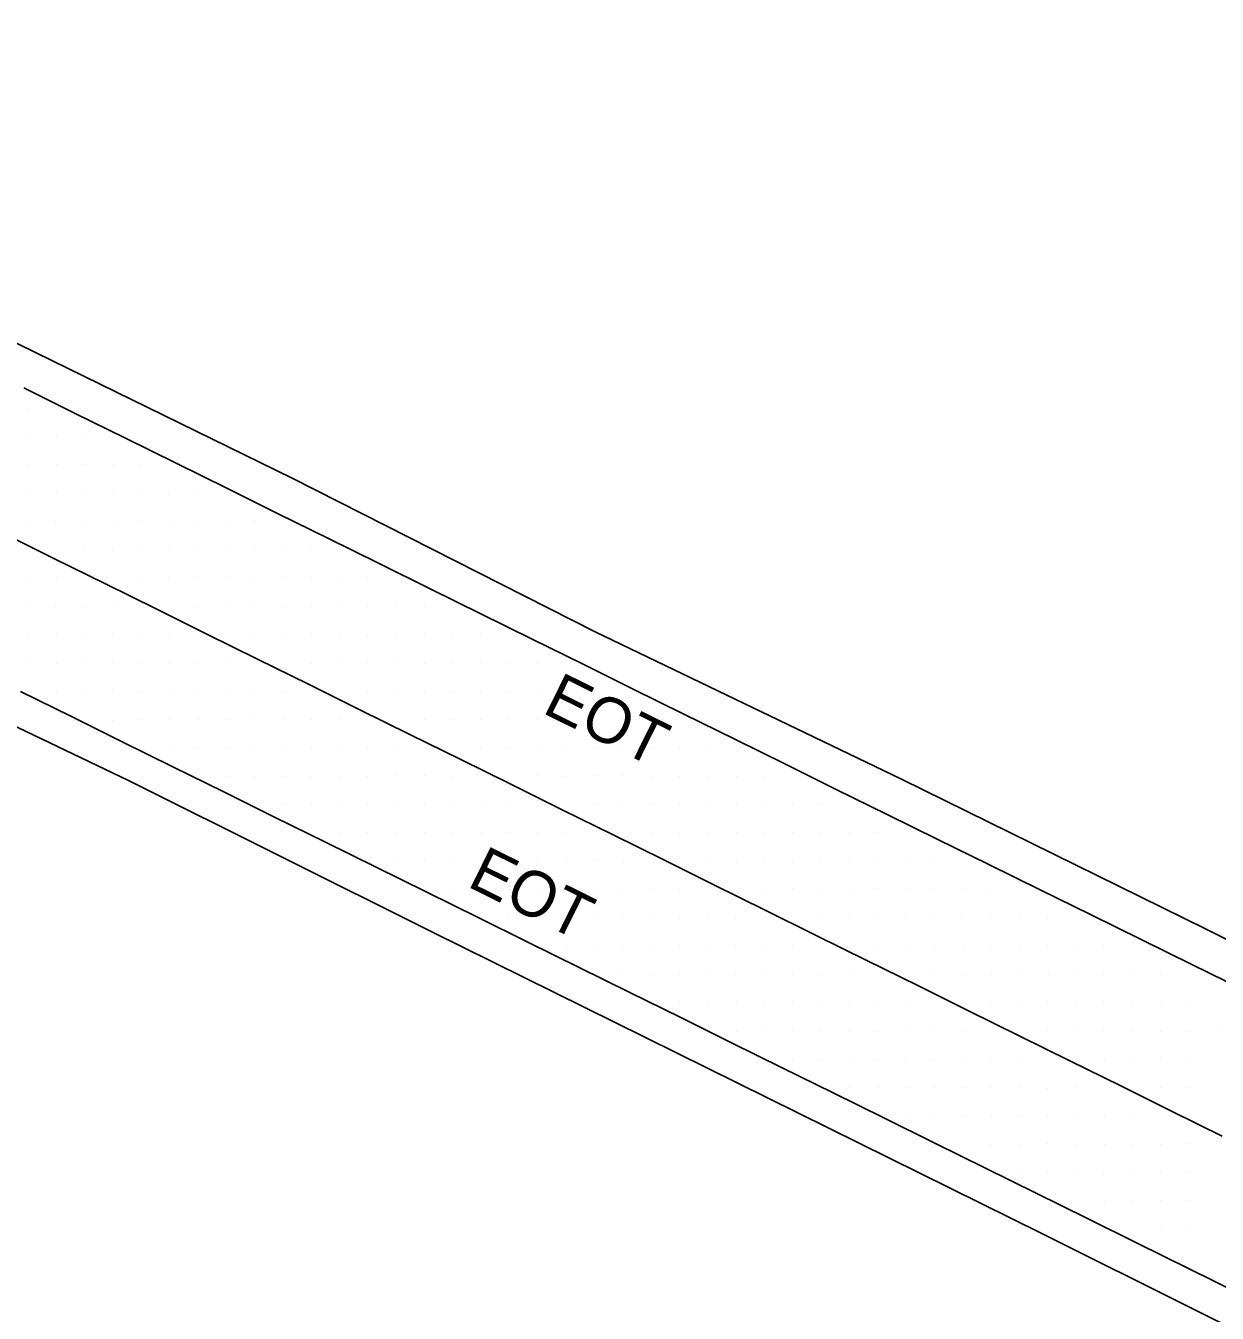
# Model space of a CAD drawing. Extents: x 2244337 to 2251208, y 199469 to 202984.
# Drawn here: x 2245321.4 to 2245426.6, y 202410.3 to 202524 of the extents above; entities that cross this region are included whole.
import ezdxf

# ---------------------------------------------------------------- set-up
doc = ezdxf.new("R2010")
doc.units = 0
for name, color, linetype in [('Exist DTM Scan Elevation Point', 7, 'Continuous'), ('Exist EOT Text', 7, 'Continuous'), ('Exist Roads EOP', 7, 'Continuous'), ('Exist Roads EOT', 7, 'Continuous')]:
    doc.layers.add(name, color=color, linetype=linetype)

msp = doc.modelspace()

# ---------------------------------------------------------------- linework, layer by layer
at = {"layer": 'Exist DTM Scan Elevation Point'}
for p, q in [((2245321.59, 202490.19), (2245321.59, 202490.19)), ((2245321.56, 202487.7), (2245321.56, 202487.7)), ((2245324.14, 202487.68), (2245324.14, 202487.68)), ((2245326.56, 202487.72), (2245326.56, 202487.72)), ((2245321.58, 202485.23), (2245321.58, 202485.23)), ((2245324.08, 202485.2), (2245324.08, 202485.2)), ((2245326.62, 202485.25), (2245326.62, 202485.25)), ((2245329.09, 202485.25), (2245329.09, 202485.25)), ((2245331.53, 202485.21), (2245331.53, 202485.21)), ((2245321.51, 202482.74), (2245321.51, 202482.74)), ((2245324.1, 202482.74), (2245324.1, 202482.74)), ((2245326.55, 202482.71), (2245326.55, 202482.71)), ((2245329.1, 202482.69), (2245329.1, 202482.69)), ((2245331.56, 202482.69), (2245331.56, 202482.69)), ((2245334.01, 202482.66), (2245334.01, 202482.66)), ((2245336.63, 202482.75), (2245336.63, 202482.75)), ((2245321.58, 202480.15), (2245321.58, 202480.15)), ((2245324.01, 202480.17), (2245324.01, 202480.17)), ((2245326.57, 202480.2), (2245326.57, 202480.2)), ((2245329.1, 202480.21), (2245329.1, 202480.21)), ((2245331.57, 202480.2), (2245331.57, 202480.2)), ((2245334.07, 202480.2), (2245334.07, 202480.2)), ((2245336.6, 202480.22), (2245336.6, 202480.22)), ((2245339.06, 202480.19), (2245339.06, 202480.19)), ((2245341.61, 202480.24), (2245341.61, 202480.24)), ((2245326.56, 202477.74), (2245326.56, 202477.74)), ((2245329.06, 202477.74), (2245329.06, 202477.74)), ((2245331.57, 202477.74), (2245331.57, 202477.74)), ((2245334.05, 202477.76), (2245334.05, 202477.76)), ((2245336.55, 202477.72), (2245336.55, 202477.72)), ((2245339.08, 202477.73), (2245339.08, 202477.73)), ((2245341.57, 202477.69), (2245341.57, 202477.69)), ((2245344.05, 202477.73), (2245344.05, 202477.73)), ((2245346.54, 202477.72), (2245346.54, 202477.72)), ((2245321.55, 202475.21), (2245321.55, 202475.21)), ((2245324.09, 202475.21), (2245324.09, 202475.21)), ((2245331.59, 202475.19), (2245331.59, 202475.19)), ((2245334, 202475.19), (2245334, 202475.19)), ((2245336.57, 202475.22), (2245336.57, 202475.22)), ((2245339.09, 202475.22), (2245339.09, 202475.22)), ((2245341.56, 202475.22), (2245341.56, 202475.22)), ((2245344.08, 202475.22), (2245344.08, 202475.22)), ((2245346.58, 202475.25), (2245346.58, 202475.25)), ((2245349.09, 202475.26), (2245349.09, 202475.26)), ((2245351.57, 202475.21), (2245351.57, 202475.21)), ((2245321.6, 202472.72), (2245321.6, 202472.72)), ((2245324.05, 202472.71), (2245324.05, 202472.71)), ((2245326.63, 202472.67), (2245326.63, 202472.67)), ((2245329.09, 202472.71), (2245329.09, 202472.71)), ((2245336.55, 202472.72), (2245336.55, 202472.72)), ((2245339.06, 202472.68), (2245339.06, 202472.68)), ((2245341.59, 202472.72), (2245341.59, 202472.72)), ((2245344.07, 202472.69), (2245344.07, 202472.69)), ((2245346.58, 202472.68), (2245346.58, 202472.68)), ((2245349.08, 202472.71), (2245349.08, 202472.71)), ((2245351.59, 202472.76), (2245351.59, 202472.76)), ((2245354.1, 202472.74), (2245354.1, 202472.74)), ((2245356.58, 202472.71), (2245356.58, 202472.71)), ((2245321.56, 202470.23), (2245321.56, 202470.23)), ((2245324.1, 202470.18), (2245324.1, 202470.18)), ((2245326.59, 202470.16), (2245326.59, 202470.16)), ((2245329.07, 202470.21), (2245329.07, 202470.21)), ((2245331.57, 202470.23), (2245331.57, 202470.23)), ((2245334.05, 202470.24), (2245334.05, 202470.24)), ((2245341.58, 202470.15), (2245341.58, 202470.15)), ((2245344.08, 202470.18), (2245344.08, 202470.18)), ((2245346.6, 202470.24), (2245346.6, 202470.24)), ((2245349.04, 202470.18), (2245349.04, 202470.18)), ((2245351.59, 202470.17), (2245351.59, 202470.17)), ((2245354.08, 202470.22), (2245354.08, 202470.22)), ((2245356.54, 202470.25), (2245356.54, 202470.25)), ((2245359.04, 202470.23), (2245359.04, 202470.23)), ((2245361.54, 202470.22), (2245361.54, 202470.22)), ((2245321.55, 202467.73), (2245321.55, 202467.73)), ((2245324.09, 202467.69), (2245324.09, 202467.69)), ((2245326.56, 202467.76), (2245326.56, 202467.76)), ((2245329.06, 202467.71), (2245329.06, 202467.71)), ((2245331.56, 202467.71), (2245331.56, 202467.71)), ((2245334.1, 202467.68), (2245334.1, 202467.68)), ((2245336.57, 202467.72), (2245336.57, 202467.72)), ((2245339.06, 202467.7), (2245339.06, 202467.7)), ((2245346.57, 202467.68), (2245346.57, 202467.68)), ((2245349.09, 202467.74), (2245349.09, 202467.74)), ((2245351.51, 202467.75), (2245351.51, 202467.75)), ((2245354.09, 202467.73), (2245354.09, 202467.73)), ((2245356.58, 202467.68), (2245356.58, 202467.68)), ((2245359.07, 202467.66), (2245359.07, 202467.66)), ((2245361.56, 202467.71), (2245361.56, 202467.71)), ((2245364.08, 202467.72), (2245364.08, 202467.72)), ((2245366.59, 202467.68), (2245366.59, 202467.68)), ((2245324.08, 202465.2), (2245324.08, 202465.2)), ((2245326.57, 202465.21), (2245326.57, 202465.21)), ((2245329.08, 202465.25), (2245329.08, 202465.25)), ((2245331.56, 202465.22), (2245331.56, 202465.22)), ((2245334.08, 202465.19), (2245334.08, 202465.19)), ((2245336.6, 202465.21), (2245336.6, 202465.21)), ((2245339.05, 202465.22), (2245339.05, 202465.22)), ((2245341.59, 202465.18), (2245341.59, 202465.18)), ((2245344.09, 202465.19), (2245344.09, 202465.19)), ((2245351.53, 202465.2), (2245351.53, 202465.2)), ((2245354.02, 202465.18), (2245354.02, 202465.18)), ((2245356.54, 202465.18), (2245356.54, 202465.18)), ((2245359.11, 202465.2), (2245359.11, 202465.2)), ((2245361.56, 202465.19), (2245361.56, 202465.19)), ((2245364.07, 202465.21), (2245364.07, 202465.21)), ((2245366.61, 202465.24), (2245366.61, 202465.24)), ((2245369.08, 202465.23), (2245369.08, 202465.23)), ((2245371.58, 202465.24), (2245371.58, 202465.24)), ((2245329.07, 202462.65), (2245329.07, 202462.65)), ((2245331.57, 202462.73), (2245331.57, 202462.73)), ((2245334.07, 202462.72), (2245334.07, 202462.72)), ((2245336.61, 202462.7), (2245336.61, 202462.7)), ((2245339.07, 202462.71), (2245339.07, 202462.71)), ((2245341.58, 202462.79), (2245341.58, 202462.79)), ((2245344.1, 202462.72), (2245344.1, 202462.72)), ((2245346.58, 202462.74), (2245346.58, 202462.74)), ((2245349.1, 202462.73), (2245349.1, 202462.73)), ((2245356.56, 202462.68), (2245356.56, 202462.68)), ((2245359.1, 202462.71), (2245359.1, 202462.71)), ((2245361.57, 202462.7), (2245361.57, 202462.7)), ((2245364.04, 202462.71), (2245364.04, 202462.71)), ((2245366.58, 202462.67), (2245366.58, 202462.67)), ((2245369.09, 202462.67), (2245369.09, 202462.67)), ((2245371.59, 202462.66), (2245371.59, 202462.66)), ((2245374.08, 202462.74), (2245374.08, 202462.74)), ((2245376.57, 202462.69), (2245376.57, 202462.69)), ((2245334.08, 202460.22), (2245334.08, 202460.22)), ((2245336.58, 202460.22), (2245336.58, 202460.22)), ((2245339.11, 202460.24), (2245339.11, 202460.24)), ((2245341.57, 202460.21), (2245341.57, 202460.21)), ((2245344.1, 202460.19), (2245344.1, 202460.19)), ((2245346.6, 202460.22), (2245346.6, 202460.22)), ((2245349.14, 202460.16), (2245349.14, 202460.16)), ((2245351.58, 202460.25), (2245351.58, 202460.25)), ((2245354.05, 202460.22), (2245354.05, 202460.22)), ((2245361.54, 202460.22), (2245361.54, 202460.22)), ((2245364.07, 202460.2), (2245364.07, 202460.2)), ((2245366.59, 202460.21), (2245366.59, 202460.21)), ((2245369.11, 202460.2), (2245369.11, 202460.2)), ((2245371.55, 202460.2), (2245371.55, 202460.2)), ((2245374.07, 202460.21), (2245374.07, 202460.21)), ((2245376.55, 202460.26), (2245376.55, 202460.26)), ((2245379.1, 202460.2), (2245379.1, 202460.2)), ((2245381.55, 202460.19), (2245381.55, 202460.19)), ((2245339.1, 202457.72), (2245339.1, 202457.72)), ((2245341.61, 202457.69), (2245341.61, 202457.69)), ((2245344.05, 202457.7), (2245344.05, 202457.7)), ((2245346.55, 202457.69), (2245346.55, 202457.69)), ((2245349.13, 202457.72), (2245349.13, 202457.72)), ((2245351.55, 202457.7), (2245351.55, 202457.7)), ((2245354.08, 202457.74), (2245354.08, 202457.74)), ((2245356.58, 202457.74), (2245356.58, 202457.74)), ((2245359.08, 202457.67), (2245359.08, 202457.67)), ((2245366.52, 202457.73), (2245366.52, 202457.73)), ((2245369.04, 202457.69), (2245369.04, 202457.69)), ((2245371.57, 202457.75), (2245371.57, 202457.75)), ((2245374.05, 202457.75), (2245374.05, 202457.75)), ((2245376.61, 202457.71), (2245376.61, 202457.71)), ((2245379.05, 202457.67), (2245379.05, 202457.67)), ((2245381.54, 202457.67), (2245381.54, 202457.67)), ((2245384.11, 202457.72), (2245384.11, 202457.72)), ((2245386.57, 202457.69), (2245386.57, 202457.69)), ((2245344.08, 202455.21), (2245344.08, 202455.21)), ((2245346.57, 202455.22), (2245346.57, 202455.22)), ((2245349.09, 202455.26), (2245349.09, 202455.26)), ((2245351.58, 202455.24), (2245351.58, 202455.24)), ((2245354.05, 202455.26), (2245354.05, 202455.26)), ((2245356.54, 202455.2), (2245356.54, 202455.2)), ((2245359.06, 202455.26), (2245359.06, 202455.26)), ((2245361.62, 202455.21), (2245361.62, 202455.21)), ((2245364.04, 202455.21), (2245364.04, 202455.21)), ((2245371.56, 202455.22), (2245371.56, 202455.22)), ((2245374.09, 202455.19), (2245374.09, 202455.19)), ((2245376.55, 202455.18), (2245376.55, 202455.18)), ((2245379.06, 202455.2), (2245379.06, 202455.2)), ((2245381.6, 202455.2), (2245381.6, 202455.2)), ((2245384.09, 202455.25), (2245384.09, 202455.25)), ((2245386.6, 202455.21), (2245386.6, 202455.21)), ((2245389.05, 202455.22), (2245389.05, 202455.22)), ((2245391.62, 202455.22), (2245391.62, 202455.22)), ((2245349.07, 202452.71), (2245349.07, 202452.71)), ((2245351.59, 202452.75), (2245351.59, 202452.75)), ((2245354.12, 202452.69), (2245354.12, 202452.69)), ((2245356.56, 202452.71), (2245356.56, 202452.71)), ((2245359.05, 202452.73), (2245359.05, 202452.73)), ((2245361.61, 202452.72), (2245361.61, 202452.72)), ((2245364.06, 202452.71), (2245364.06, 202452.71)), ((2245366.57, 202452.76), (2245366.57, 202452.76)), ((2245369.06, 202452.68), (2245369.06, 202452.68)), ((2245376.61, 202452.73), (2245376.61, 202452.73)), ((2245379.07, 202452.68), (2245379.07, 202452.68)), ((2245381.58, 202452.7), (2245381.58, 202452.7)), ((2245384.09, 202452.74), (2245384.09, 202452.74)), ((2245386.56, 202452.74), (2245386.56, 202452.74)), ((2245389.04, 202452.69), (2245389.04, 202452.69)), ((2245391.56, 202452.71), (2245391.56, 202452.71)), ((2245394.11, 202452.71), (2245394.11, 202452.71)), ((2245396.58, 202452.69), (2245396.58, 202452.69)), ((2245354.14, 202450.25), (2245354.14, 202450.25)), ((2245356.55, 202450.22), (2245356.55, 202450.22)), ((2245359.04, 202450.24), (2245359.04, 202450.24)), ((2245361.58, 202450.22), (2245361.58, 202450.22)), ((2245364.07, 202450.21), (2245364.07, 202450.21)), ((2245366.55, 202450.17), (2245366.55, 202450.17)), ((2245369.08, 202450.21), (2245369.08, 202450.21)), ((2245371.58, 202450.23), (2245371.58, 202450.23)), ((2245374.16, 202450.21), (2245374.16, 202450.21)), ((2245381.59, 202450.24), (2245381.59, 202450.24)), ((2245384.1, 202450.21), (2245384.1, 202450.21)), ((2245386.55, 202450.2), (2245386.55, 202450.2)), ((2245389.07, 202450.21), (2245389.07, 202450.21)), ((2245391.54, 202450.18), (2245391.54, 202450.18)), ((2245394.09, 202450.21), (2245394.09, 202450.21)), ((2245396.58, 202450.2), (2245396.58, 202450.2)), ((2245399.08, 202450.25), (2245399.08, 202450.25)), ((2245401.57, 202450.23), (2245401.57, 202450.23)), ((2245359.09, 202447.71), (2245359.09, 202447.71)), ((2245361.58, 202447.73), (2245361.58, 202447.73)), ((2245364.05, 202447.72), (2245364.05, 202447.72)), ((2245366.6, 202447.69), (2245366.6, 202447.69)), ((2245369.04, 202447.72), (2245369.04, 202447.72)), ((2245371.54, 202447.73), (2245371.54, 202447.73)), ((2245374.07, 202447.7), (2245374.07, 202447.7)), ((2245376.52, 202447.71), (2245376.52, 202447.71)), ((2245379.11, 202447.72), (2245379.11, 202447.72)), ((2245386.63, 202447.71), (2245386.63, 202447.71)), ((2245389.07, 202447.77), (2245389.07, 202447.77)), ((2245391.56, 202447.68), (2245391.56, 202447.68)), ((2245394.08, 202447.7), (2245394.08, 202447.7)), ((2245396.6, 202447.75), (2245396.6, 202447.75)), ((2245399.1, 202447.72), (2245399.1, 202447.72)), ((2245401.51, 202447.68), (2245401.51, 202447.68)), ((2245404.05, 202447.71), (2245404.05, 202447.71)), ((2245406.56, 202447.7), (2245406.56, 202447.7)), ((2245364.04, 202445.21), (2245364.04, 202445.21)), ((2245366.61, 202445.2), (2245366.61, 202445.2)), ((2245369.1, 202445.21), (2245369.1, 202445.21)), ((2245371.56, 202445.23), (2245371.56, 202445.23)), ((2245374.06, 202445.21), (2245374.06, 202445.21)), ((2245376.52, 202445.2), (2245376.52, 202445.2)), ((2245379.11, 202445.19), (2245379.11, 202445.19)), ((2245381.6, 202445.23), (2245381.6, 202445.23)), ((2245384.03, 202445.2), (2245384.03, 202445.2)), ((2245391.59, 202445.25), (2245391.59, 202445.25)), ((2245394.1, 202445.23), (2245394.1, 202445.23)), ((2245396.54, 202445.19), (2245396.54, 202445.19)), ((2245399.04, 202445.21), (2245399.04, 202445.21)), ((2245401.53, 202445.2), (2245401.53, 202445.2)), ((2245404.01, 202445.19), (2245404.01, 202445.19)), ((2245406.55, 202445.2), (2245406.55, 202445.2)), ((2245409.1, 202445.21), (2245409.1, 202445.21)), ((2245411.59, 202445.21), (2245411.59, 202445.21)), ((2245369.09, 202442.71), (2245369.09, 202442.71)), ((2245371.56, 202442.65), (2245371.56, 202442.65)), ((2245374.09, 202442.71), (2245374.09, 202442.71)), ((2245376.57, 202442.7), (2245376.57, 202442.7)), ((2245379.11, 202442.69), (2245379.11, 202442.69)), ((2245381.63, 202442.73), (2245381.63, 202442.73)), ((2245384.07, 202442.72), (2245384.07, 202442.72)), ((2245386.6, 202442.73), (2245386.6, 202442.73)), ((2245389.05, 202442.69), (2245389.05, 202442.69)), ((2245396.53, 202442.7), (2245396.53, 202442.7)), ((2245399.1, 202442.69), (2245399.1, 202442.69)), ((2245401.58, 202442.7), (2245401.58, 202442.7)), ((2245404.12, 202442.7), (2245404.12, 202442.7)), ((2245406.56, 202442.69), (2245406.56, 202442.69)), ((2245409.1, 202442.7), (2245409.1, 202442.7)), ((2245411.6, 202442.71), (2245411.6, 202442.71)), ((2245414.08, 202442.72), (2245414.08, 202442.72)), ((2245416.54, 202442.71), (2245416.54, 202442.71)), ((2245374.08, 202440.21), (2245374.08, 202440.21)), ((2245376.51, 202440.21), (2245376.51, 202440.21)), ((2245379.06, 202440.21), (2245379.06, 202440.21)), ((2245381.59, 202440.23), (2245381.59, 202440.23)), ((2245384.07, 202440.2), (2245384.07, 202440.2)), ((2245386.59, 202440.18), (2245386.59, 202440.18)), ((2245389.07, 202440.24), (2245389.07, 202440.24)), ((2245391.63, 202440.18), (2245391.63, 202440.18)), ((2245394.07, 202440.19), (2245394.07, 202440.19)), ((2245401.6, 202440.23), (2245401.6, 202440.23)), ((2245404.04, 202440.17), (2245404.04, 202440.17)), ((2245406.61, 202440.19), (2245406.61, 202440.19)), ((2245409.08, 202440.21), (2245409.08, 202440.21)), ((2245411.65, 202440.19), (2245411.65, 202440.19)), ((2245414.08, 202440.22), (2245414.08, 202440.22)), ((2245416.52, 202440.22), (2245416.52, 202440.22)), ((2245419.06, 202440.18), (2245419.06, 202440.18)), ((2245421.58, 202440.22), (2245421.58, 202440.22)), ((2245379.07, 202437.76), (2245379.07, 202437.76)), ((2245381.61, 202437.7), (2245381.61, 202437.7)), ((2245384.1, 202437.69), (2245384.1, 202437.69)), ((2245386.55, 202437.7), (2245386.55, 202437.7)), ((2245389.06, 202437.72), (2245389.06, 202437.72)), ((2245391.62, 202437.74), (2245391.62, 202437.74)), ((2245394.09, 202437.72), (2245394.09, 202437.72)), ((2245396.61, 202437.75), (2245396.61, 202437.75)), ((2245399.09, 202437.75), (2245399.09, 202437.75)), ((2245406.56, 202437.71), (2245406.56, 202437.71)), ((2245409.02, 202437.72), (2245409.02, 202437.72)), ((2245411.61, 202437.74), (2245411.61, 202437.74)), ((2245414.08, 202437.69), (2245414.08, 202437.69)), ((2245416.55, 202437.75), (2245416.55, 202437.75)), ((2245419.09, 202437.71), (2245419.09, 202437.71)), ((2245421.61, 202437.69), (2245421.61, 202437.69)), ((2245424.09, 202437.69), (2245424.09, 202437.69)), ((2245384.1, 202435.2), (2245384.1, 202435.2)), ((2245386.59, 202435.24), (2245386.59, 202435.24)), ((2245389.04, 202435.22), (2245389.04, 202435.22)), ((2245391.57, 202435.17), (2245391.57, 202435.17)), ((2245394.06, 202435.19), (2245394.06, 202435.19)), ((2245396.58, 202435.19), (2245396.58, 202435.19)), ((2245399.02, 202435.21), (2245399.02, 202435.21)), ((2245401.57, 202435.22), (2245401.57, 202435.22)), ((2245404.09, 202435.22), (2245404.09, 202435.22)), ((2245411.61, 202435.23), (2245411.61, 202435.23)), ((2245414.06, 202435.25), (2245414.06, 202435.25)), ((2245416.56, 202435.21), (2245416.56, 202435.21)), ((2245419.1, 202435.18), (2245419.1, 202435.18)), ((2245421.57, 202435.18), (2245421.57, 202435.18)), ((2245424.1, 202435.19), (2245424.1, 202435.19)), ((2245426.56, 202435.25), (2245426.56, 202435.25)), ((2245389.05, 202432.68), (2245389.05, 202432.68)), ((2245391.61, 202432.68), (2245391.61, 202432.68)), ((2245394.08, 202432.7), (2245394.08, 202432.7)), ((2245396.58, 202432.68), (2245396.58, 202432.68)), ((2245399.08, 202432.74), (2245399.08, 202432.74)), ((2245401.53, 202432.69), (2245401.53, 202432.69)), ((2245404.1, 202432.76), (2245404.1, 202432.76)), ((2245406.57, 202432.75), (2245406.57, 202432.75)), ((2245409.12, 202432.7), (2245409.12, 202432.7)), ((2245416.58, 202432.69), (2245416.58, 202432.69)), ((2245419.09, 202432.69), (2245419.09, 202432.69)), ((2245421.57, 202432.74), (2245421.57, 202432.74)), ((2245424.04, 202432.69), (2245424.04, 202432.69)), ((2245394.06, 202430.21), (2245394.06, 202430.21)), ((2245396.63, 202430.19), (2245396.63, 202430.19)), ((2245399.1, 202430.22), (2245399.1, 202430.22)), ((2245401.58, 202430.25), (2245401.58, 202430.25)), ((2245404.07, 202430.24), (2245404.07, 202430.24)), ((2245406.51, 202430.22), (2245406.51, 202430.22)), ((2245409.13, 202430.19), (2245409.13, 202430.19)), ((2245411.62, 202430.16), (2245411.62, 202430.16)), ((2245414.07, 202430.24), (2245414.07, 202430.24)), ((2245421.54, 202430.22), (2245421.54, 202430.22)), ((2245424.11, 202430.2), (2245424.11, 202430.2)), ((2245399.08, 202427.71), (2245399.08, 202427.71)), ((2245401.61, 202427.69), (2245401.61, 202427.69)), ((2245404.06, 202427.7), (2245404.06, 202427.7)), ((2245406.6, 202427.65), (2245406.6, 202427.65)), ((2245409.05, 202427.73), (2245409.05, 202427.73)), ((2245411.58, 202427.7), (2245411.58, 202427.7)), ((2245414.01, 202427.74), (2245414.01, 202427.74)), ((2245416.59, 202427.71), (2245416.59, 202427.71)), ((2245419.06, 202427.76), (2245419.06, 202427.76)), ((2245406.57, 202425.22), (2245406.57, 202425.22)), ((2245409.09, 202425.22), (2245409.09, 202425.22)), ((2245411.6, 202425.26), (2245411.6, 202425.26)), ((2245414.07, 202425.19), (2245414.07, 202425.19)), ((2245416.63, 202425.18), (2245416.63, 202425.18)), ((2245419.08, 202425.2), (2245419.08, 202425.2)), ((2245421.59, 202425.19), (2245421.59, 202425.19)), ((2245424.08, 202425.23), (2245424.08, 202425.23)), ((2245409.09, 202422.74), (2245409.09, 202422.74)), ((2245411.55, 202422.72), (2245411.55, 202422.72)), ((2245414.08, 202422.72), (2245414.08, 202422.72)), ((2245416.54, 202422.66), (2245416.54, 202422.66)), ((2245419.1, 202422.72), (2245419.1, 202422.72)), ((2245421.59, 202422.67), (2245421.59, 202422.67)), ((2245424.1, 202422.72), (2245424.1, 202422.72)), ((2245416.59, 202420.16), (2245416.59, 202420.16)), ((2245419.04, 202420.22), (2245419.04, 202420.22)), ((2245421.59, 202420.22), (2245421.59, 202420.22)), ((2245424.13, 202420.21), (2245424.13, 202420.21)), ((2245421.6, 202417.7), (2245421.6, 202417.7)), ((2245424.1, 202417.71), (2245424.1, 202417.71))]:
    msp.add_line(p, q, dxfattribs=at)
at = {"layer": 'Exist Roads EOP'}
for points in [[(2244914.92, 202697.38), (2244941.73, 202683.92), (2244968.6, 202670.56), (2244995.44, 202657.14), (2245022.46, 202644.11), (2245049.07, 202630.25), (2245075.97, 202616.98), (2245102.89, 202603.74), (2245129.82, 202590.53), (2245156.74, 202577.27), (2245183.52, 202563.74), (2245210.45, 202550.53), (2245237.23, 202537.02), (2245264.11, 202523.69), (2245290.97, 202510.33), (2245317.95, 202497.21), (2245344.9, 202484.03), (2245371.65, 202470.44), (2245398.68, 202457.45), (2245425.59, 202444.19), (2245452.43, 202430.78), (2245479.31, 202417.45), (2245506.2, 202404.14), (2245533.29, 202391.24)], [(2245545.53, 202350.85), (2245518.62, 202364.12), (2245491.72, 202377.38), (2245464.95, 202390.93), (2245437.92, 202403.94), (2245411.07, 202417.34), (2245384.18, 202430.64), (2245357.28, 202443.93), (2245330.44, 202457.32), (2245303.38, 202470.27)]]:
    msp.add_lwpolyline(points, dxfattribs=at)
at = {"layer": 'Exist Roads EOT'}
for points in [[(2245321.21, 202491.99), (2245325.7, 202489.77), (2245330.18, 202487.56), (2245334.66, 202485.34), (2245339.14, 202483.12), (2245343.62, 202480.91), (2245348.1, 202478.69), (2245352.59, 202476.47), (2245357.07, 202474.26), (2245361.55, 202472.04), (2245366.03, 202469.83), (2245370.52, 202467.61), (2245375, 202465.4), (2245379.48, 202463.18), (2245383.97, 202460.97), (2245388.45, 202458.76), (2245392.93, 202456.54), (2245397.42, 202454.33), (2245401.9, 202452.12), (2245406.39, 202449.91), (2245410.87, 202447.7), (2245415.36, 202445.49), (2245419.84, 202443.28), (2245424.33, 202441.07), (2245428.81, 202438.86)], [(2245319.44, 202479.12), (2245323.92, 202476.9), (2245328.41, 202474.69), (2245332.89, 202472.47), (2245337.37, 202470.25), (2245341.85, 202468.04), (2245346.33, 202465.82), (2245350.82, 202463.6), (2245355.3, 202461.39), (2245359.78, 202459.17), (2245364.26, 202456.96), (2245368.74, 202454.74), (2245373.23, 202452.52), (2245377.71, 202450.31), (2245382.19, 202448.09), (2245386.67, 202445.87), (2245391.15, 202443.65), (2245395.63, 202441.44), (2245400.12, 202439.22), (2245404.6, 202437), (2245409.08, 202434.78), (2245413.56, 202432.57), (2245418.04, 202430.35), (2245422.52, 202428.13), (2245427, 202425.91)], [(2245428.51, 202412.02), (2245424.03, 202414.23), (2245419.55, 202416.45), (2245415.06, 202418.67), (2245410.58, 202420.88), (2245406.1, 202423.1), (2245401.62, 202425.31), (2245397.14, 202427.53), (2245392.65, 202429.74), (2245388.17, 202431.96), (2245383.69, 202434.17), (2245379.21, 202436.39), (2245374.72, 202438.61), (2245370.24, 202440.82), (2245365.76, 202443.03), (2245361.27, 202445.25), (2245356.79, 202447.46), (2245352.31, 202449.68), (2245347.83, 202451.89), (2245343.34, 202454.1), (2245338.86, 202456.32), (2245334.38, 202458.53), (2245329.89, 202460.75), (2245325.41, 202462.96), (2245320.93, 202465.17)]]:
    msp.add_lwpolyline(points, dxfattribs=at)

# ---------------------------------------------------------------- texts
at = {"layer": 'Exist EOT Text'}
for rotation, p in [(333.6949, (2245366.87, 202463.35)), (333.6933, (2245360.24, 202448.03))]:
    msp.add_text('EOT', height=4.02, rotation=rotation, dxfattribs=at).set_placement(p)

doc.saveas('drawing.dxf')
